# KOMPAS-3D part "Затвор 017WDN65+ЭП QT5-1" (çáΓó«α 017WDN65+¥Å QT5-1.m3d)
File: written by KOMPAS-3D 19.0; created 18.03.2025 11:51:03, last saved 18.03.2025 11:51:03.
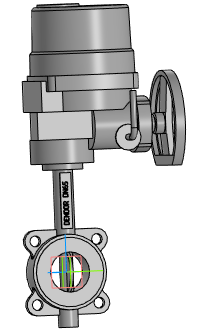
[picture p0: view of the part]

Document properties: Полное имя файла: Затвор 017WDN65+ЭП QT5-1.a3d

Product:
- Part/product: Затвор 017WDN65+ЭП QT5-1
    Масса: 44.5154

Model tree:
1. Операция без истории:1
